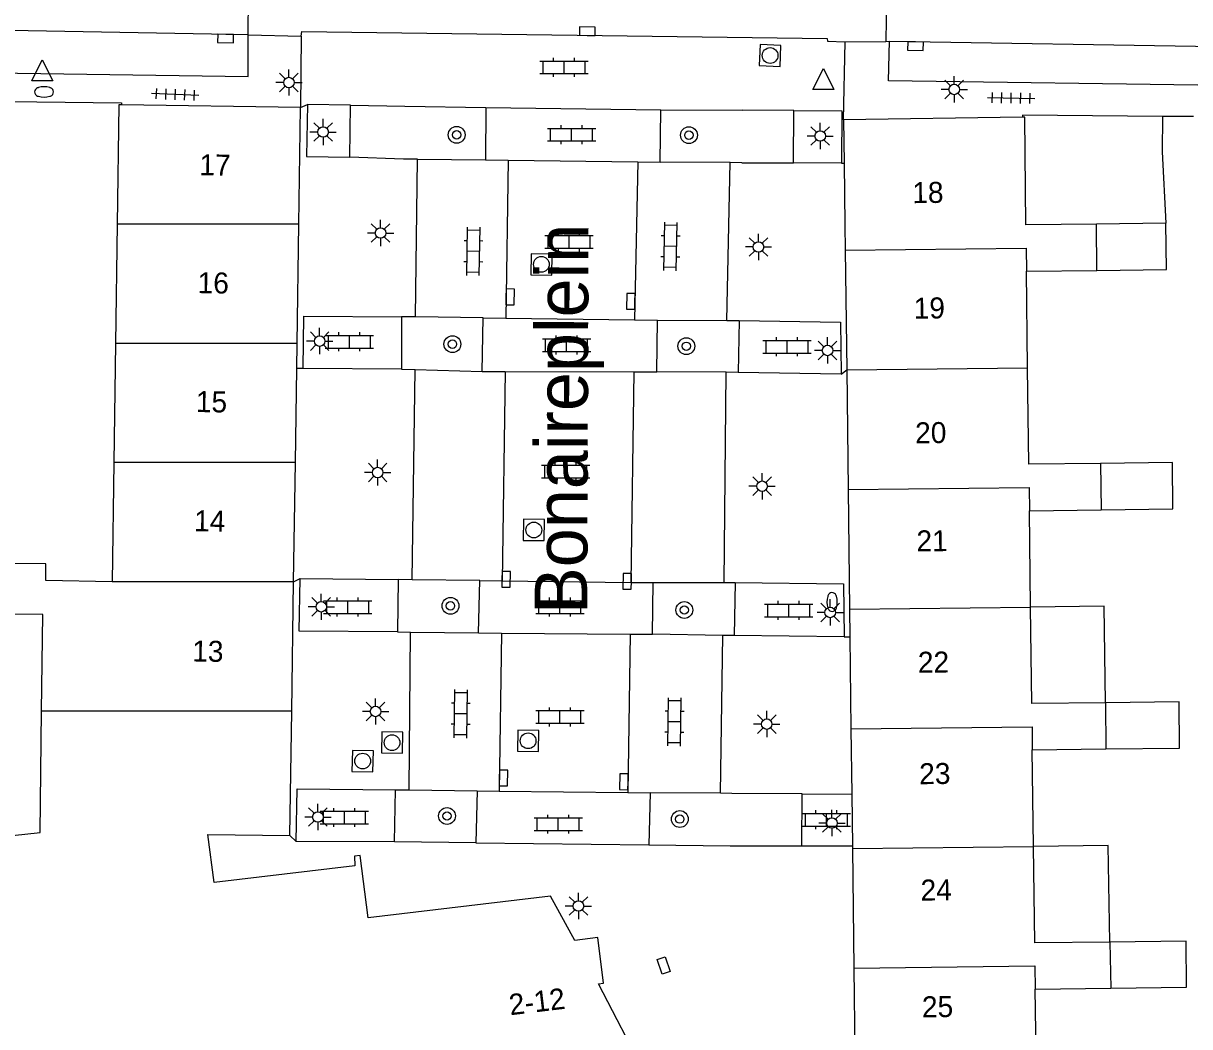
# Model space of a CAD drawing. Extents: x 132999 to 136000, y 398499 to 400501.
# Drawn here: x 133616.6 to 133672.1, y 398546.3 to 398594.1 of the extents above; entities that cross this region are included whole.
import ezdxf

# ---------------------------------------------------------------- set-up
doc = ezdxf.new("R2010")
doc.units = 0
for name, color, linetype in [('gg-afsc-erfafscheiding', 7, 'Continuous'), ('gg-afsc-muur', 7, 'Continuous'), ('gg-anno-huisnummerreeks BGT', 7, 'Continuous'), ('gg-anno-openbare ruimte label', 7, 'Continuous'), ('gg-bbg-bijgebouw', 7, 'Continuous'), ('gg-bbg-hoofdgebouw', 7, 'Continuous'), ('gg-bbg-luifel en loopbrug', 7, 'Continuous'), ('gg-bbg-tussenscheiding', 7, 'Continuous'), ('gg-knt-verharding', 7, 'Continuous'), ('gg-knt-verharding nz', 7, 'Continuous'), ('gt-grn-weggrens', 7, 'Continuous'), ('gt-symb-boom', 7, 'Continuous'), ('gt-symb-brandkraan', 7, 'Continuous'), ('gt-symb-klinker verharding', 7, 'Continuous'), ('gt-symb-kolk', 7, 'Continuous'), ('gt-symb-kolk center center', 7, 'Continuous'), ('gt-symb-lichtmast', 7, 'Continuous'), ('gt-symb-rioolschacht', 7, 'Continuous'), ('gt-symb-tegel verharding', 7, 'Continuous'), ('gt-symb-waterafsluiter', 7, 'Continuous')]:
    doc.layers.add(name, color=color, linetype=linetype)

# ---------------------------------------------------------------- blocks, each defined once
blk = doc.blocks.new('gt0-BR')
at = {"layer": 'gt-symb-brandkraan'}
for centre, radius, start, end in [((-0.244, 0), 0.206, 107.5669, 252.4331), ((0.599, -2.664), 3, 106.892, 107.5669), ((0, -0.691), 0.938, 73.108, 106.892), ((-0.599, -2.664), 3, 72.4331, 73.108), ((0.244, 0), 0.206, 287.567, 72.4331), ((0.599, 2.664), 3, 252.4331, 253.108), ((0, 0.691), 0.938, 253.108, 286.8921), ((-0.599, 2.664), 3, 286.8921, 287.567)]:
    blk.add_arc(centre, radius, start, end, dxfattribs=at)
blk = doc.blocks.new('gt0-LMAST')
at = {"layer": 'gt-symb-lichtmast'}
for p, q in [((-0.005, 0.246), (-0.005, 0.621)), ((-0.182, 0.173), (-0.447, 0.438)), ((0.172, 0.173), (0.437, 0.438)), ((-0.255, -0.004), (-0.63, -0.004)), ((-0.182, -0.181), (-0.447, -0.446)), ((-0.005, -0.254), (-0.005, -0.629)), ((0.437, -0.446), (0.172, -0.181)), ((0.245, -0.004), (0.62, -0.004))]:
    blk.add_line(p, q, dxfattribs=at)
blk.add_circle((-0.005, -0.004), 0.25, dxfattribs=at)
blk = doc.blocks.new('gt0-TEG1')
at = {"layer": 'gt-symb-tegel verharding'}
for p, q in [((-1.125, 0), (1.125, 0)), ((-0.9, -0.25), (-0.9, 0.25)), ((-0.45, -0.25), (-0.45, 0.25)), ((0, -0.25), (0, 0.25)), ((0.45, -0.25), (0.45, 0.25)), ((0.9, -0.25), (0.9, 0.25))]:
    blk.add_line(p, q, dxfattribs=at)
blk = doc.blocks.new('gt0-WAFSL')
at = {"layer": 'gt-symb-waterafsluiter'}
for p, q in [((-0.5, -0.333), (0, 0.667)), ((0, 0.667), (0.5, -0.333)), ((0.5, -0.333), (-0.5, -0.333))]:
    blk.add_line(p, q, dxfattribs=at)
blk = doc.blocks.new('gt0-KOLK')
at = {"layer": 'gt-symb-kolk'}
blk.add_lwpolyline([(0, 0), (0.375, 0), (0.375, 0.4), (-0.375, 0.4), (-0.375, 0), (0, 0)], dxfattribs=at)
blk = doc.blocks.new('gt0-KL1')
at = {"layer": 'gt-symb-klinker verharding'}
for p, q in [((-1.15, 0.3), (1.15, 0.3)), ((-1, -0.3), (-1, 0.3)), ((-0.5, 0.3), (-0.5, 0.45)), ((0, -0.3), (0, 0.3)), ((0.5, 0.3), (0.5, 0.45)), ((1, -0.3), (1, 0.3)), ((-1.15, -0.3), (1.15, -0.3)), ((-0.5, -0.45), (-0.5, -0.3)), ((0.5, -0.45), (0.5, -0.3))]:
    blk.add_line(p, q, dxfattribs=at)
blk = doc.blocks.new('gt0-RS')
at = {"layer": 'gt-symb-rioolschacht'}
blk.add_lwpolyline([(-0.5, -0.5), (0.5, -0.5), (0.5, 0.5), (-0.5, 0.5)], close=True, dxfattribs=at)
blk.add_circle((0, 0), 0.375, dxfattribs=at)
blk = doc.blocks.new('gt0-KOLKCC')
at = {"layer": 'gt-symb-kolk center center'}
blk.add_lwpolyline([(-0.375, 0.2), (0.375, 0.2), (0.375, -0.2), (-0.375, -0.2)], close=True, dxfattribs=at)
blk = doc.blocks.new('gt0-BOOM')
at = {"layer": 'gt-symb-boom'}
for radius in [0.4, 0.2]:
    blk.add_circle((0, 0), radius, dxfattribs=at)

msp = doc.modelspace()

# ---------------------------------------------------------------- linework, layer by layer
at = {"layer": 'gg-afsc-erfafscheiding'}
msp.add_line((133670.827, 398587.956), (133671.01, 398584.549), dxfattribs=at)
at = {"layer": 'gg-afsc-muur'}
msp.add_line((133670.846, 398589.624), (133670.827, 398587.956), dxfattribs=at)
for points in [[(133614.572, 398590.368), (133621.298, 398590.274), (133621.297, 398590.18)], [(133670.846, 398589.624), (133664.19, 398589.7), (133664.189, 398589.593)]]:
    msp.add_lwpolyline(points, dxfattribs=at)
at = {"layer": 'gg-bbg-bijgebouw'}
msp.add_line((133671.01, 398584.549), (133667.705, 398584.508), dxfattribs=at)
for points in [[(133667.732, 398582.306), (133671.036, 398582.347), (133671.01, 398584.549)], [(133667.929, 398570.905), (133671.343, 398570.947), (133671.319, 398573.155), (133667.903, 398573.113)], [(133668.158, 398559.518), (133671.661, 398559.561), (133671.636, 398561.762), (133668.132, 398561.719)], [(133668.393, 398548.126), (133671.992, 398548.17), (133671.97, 398550.37), (133668.35, 398550.326)]]:
    msp.add_lwpolyline(points, dxfattribs=at)
at = {"layer": 'gg-bbg-hoofdgebouw'}
for p, q in [((133629.826, 398590.055), (133621.297, 398590.18)), ((133629.744, 398584.505), (133629.826, 398590.055)), ((133664.189, 398589.593), (133655.667, 398589.474)), ((133655.667, 398589.474), (133655.696, 398587.409)), ((133621.1, 398584.505), (133621.019, 398578.828)), ((133629.66, 398578.828), (133629.744, 398584.505)), ((133655.751, 398583.268), (133655.819, 398577.567)), ((133664.375, 398582.265), (133667.732, 398582.306)), ((133664.431, 398577.668), (133664.375, 398582.265)), ((133621.019, 398578.828), (133620.939, 398573.15)), ((133629.642, 398577.638), (133629.66, 398578.828)), ((133629.576, 398573.15), (133629.642, 398577.638)), ((133655.819, 398577.567), (133655.886, 398571.869)), ((133620.939, 398573.15), (133620.858, 398567.473)), ((133629.492, 398567.473), (133629.576, 398573.15)), ((133655.886, 398571.869), (133655.953, 398566.168)), ((133664.515, 398570.863), (133667.929, 398570.905)), ((133664.571, 398566.27), (133664.515, 398570.863)), ((133629.401, 398561.312), (133629.492, 398567.473)), ((133655.953, 398566.168), (133655.968, 398564.859)), ((133655.968, 398564.859), (133656.02, 398560.477)), ((133629.313, 398555.39), (133629.401, 398561.312)), ((133656.02, 398560.477), (133656.057, 398557.371)), ((133664.654, 398559.475), (133668.158, 398559.518)), ((133664.711, 398554.878), (133664.654, 398559.475)), ((133656.057, 398557.371), (133656.087, 398554.901)), ((133656.087, 398554.901), (133656.088, 398554.777)), ((133656.088, 398554.777), (133656.155, 398549.083)), ((133656.155, 398549.083), (133656.221, 398543.472)), ((133664.794, 398548.082), (133668.393, 398548.126)), ((133664.844, 398543.987), (133664.794, 398548.082))]:
    msp.add_line(p, q, dxfattribs=at)
for points in [[(133621.297, 398590.18), (133621.181, 398590.182), (133621.1, 398584.505)], [(133667.705, 398584.508), (133664.353, 398584.467), (133664.3, 398589.595), (133664.189, 398589.593)], [(133655.696, 398587.409), (133655.737, 398584.474), (133655.751, 398583.268)], [(133667.903, 398573.113), (133664.488, 398573.071), (133664.431, 398577.668)], [(133620.858, 398567.473), (133617.696, 398567.541), (133617.697, 398568.328), (133612.025, 398568.386)], [(133617.494, 398561.312), (133617.549, 398565.927), (133612.589, 398565.969)], [(133668.132, 398561.719), (133664.627, 398561.676), (133664.571, 398566.27)], [(133614.909, 398552.815), (133614.531, 398555.957), (133614.85, 398555.991), (133614.927, 398555.27), (133617.425, 398555.536), (133617.494, 398561.312)], [(133646.218, 398544.077), (133643.998, 398548.332), (133644.246, 398548.363), (133643.974, 398550.536), (133642.872, 398550.397), (133641.715, 398552.513), (133633.036, 398551.479), (133632.655, 398554.448), (133632.386, 398554.413), (133632.406, 398553.947), (133625.716, 398553.167), (133625.414, 398555.446), (133629.313, 398555.39)], [(133668.35, 398550.326), (133664.767, 398550.282), (133664.711, 398554.878)]]:
    msp.add_lwpolyline(points, dxfattribs=at)
at = {"layer": 'gg-bbg-luifel en loopbrug'}
for points in [[(133668.132, 398561.719), (133668.078, 398566.312), (133664.571, 398566.27)], [(133668.35, 398550.326), (133668.26, 398554.92), (133664.711, 398554.878)]]:
    msp.add_lwpolyline(points, dxfattribs=at)
at = {"layer": 'gg-bbg-tussenscheiding'}
for p, q in [((133629.744, 398584.505), (133621.1, 398584.505)), ((133667.732, 398582.306), (133667.705, 398584.508)), ((133629.66, 398578.828), (133621.019, 398578.828)), ((133655.819, 398577.567), (133664.431, 398577.668)), ((133629.576, 398573.15), (133620.939, 398573.15)), ((133667.903, 398573.113), (133667.929, 398570.905)), ((133629.492, 398567.473), (133620.858, 398567.473)), ((133655.953, 398566.168), (133664.571, 398566.27)), ((133668.132, 398561.719), (133668.158, 398559.518)), ((133629.401, 398561.312), (133617.494, 398561.312)), ((133656.088, 398554.777), (133664.711, 398554.878)), ((133668.35, 398550.326), (133668.393, 398548.126))]:
    msp.add_line(p, q, dxfattribs=at)
for points in [[(133655.751, 398583.268), (133664.362, 398583.369), (133664.375, 398582.265)], [(133655.886, 398571.869), (133664.501, 398571.97), (133664.515, 398570.863)], [(133656.02, 398560.477), (133664.641, 398560.579), (133664.654, 398559.475)], [(133656.155, 398549.083), (133664.78, 398549.185), (133664.794, 398548.082)]]:
    msp.add_lwpolyline(points, dxfattribs=at)
at = {"layer": 'gg-knt-verharding'}
for p, q in [((133627.329, 398593.521), (133627.377, 398598.367)), ((133657.763, 398597.706), (133657.681, 398593.209)), ((133627.329, 398593.521), (133629.847, 398593.456)), ((133629.847, 398593.456), (133629.826, 398590.055)), ((133654.905, 398593.213), (133655.741, 398593.186)), ((133655.667, 398589.474), (133655.741, 398593.186)), ((133655.741, 398593.186), (133657.681, 398593.209)), ((133657.681, 398593.209), (133657.861, 398593.211)), ((133632.164, 398587.693), (133632.206, 398590.172)), ((133632.206, 398590.172), (133634.787, 398590.128)), ((133634.787, 398590.128), (133638.645, 398590.062)), ((133638.645, 398590.062), (133638.626, 398587.563)), ((133638.645, 398590.062), (133646.971, 398589.949)), ((133646.944, 398587.462), (133646.971, 398589.949)), ((133646.971, 398589.949), (133650.877, 398589.927)), ((133653.301, 398589.913), (133650.877, 398589.927)), ((133653.287, 398587.423), (133653.301, 398589.913)), ((133672.333, 398589.623), (133670.846, 398589.624)), ((133634.73, 398587.599), (133632.164, 398587.693)), ((133635.386, 398587.593), (133634.73, 398587.599)), ((133635.386, 398587.593), (133638.626, 398587.563)), ((133638.626, 398587.563), (133639.699, 398587.55)), ((133639.699, 398587.55), (133645.879, 398587.475)), ((133645.879, 398587.475), (133646.944, 398587.462)), ((133650.269, 398587.436), (133646.944, 398587.462)), ((133650.822, 398587.432), (133650.269, 398587.436)), ((133650.822, 398587.432), (133653.287, 398587.423)), ((133634.635, 398580.098), (133634.629, 398577.602)), ((133635.3, 398580.088), (133634.635, 398580.098)), ((133638.508, 398580.039), (133635.3, 398580.088)), ((133638.474, 398577.495), (133638.508, 398580.039)), ((133638.508, 398580.039), (133639.593, 398580.025)), ((133639.593, 398580.025), (133645.72, 398579.947)), ((133645.72, 398579.947), (133646.806, 398579.933)), ((133646.784, 398577.471), (133646.806, 398579.933)), ((133646.806, 398579.933), (133650.11, 398579.914)), ((133650.11, 398579.914), (133650.701, 398579.911)), ((133650.701, 398579.911), (133650.653, 398577.448)), ((133634.629, 398577.602), (133635.277, 398577.584)), ((133635.277, 398577.584), (133638.474, 398577.495)), ((133638.474, 398577.495), (133639.558, 398577.492)), ((133639.558, 398577.492), (133645.691, 398577.474)), ((133645.691, 398577.474), (133646.784, 398577.471)), ((133650.085, 398577.451), (133646.784, 398577.471)), ((133650.653, 398577.448), (133650.085, 398577.451)), ((133634.475, 398567.579), (133634.438, 398565.092)), ((133635.134, 398567.573), (133634.475, 398567.579)), ((133638.353, 398567.541), (133635.134, 398567.573)), ((133638.289, 398565.042), (133638.353, 398567.541)), ((133638.353, 398567.541), (133639.418, 398567.527)), ((133639.418, 398567.527), (133645.546, 398567.45)), ((133645.546, 398567.45), (133646.613, 398567.436)), ((133646.573, 398564.976), (133646.613, 398567.436)), ((133646.613, 398567.436), (133649.98, 398567.448)), ((133649.98, 398567.448), (133650.511, 398567.45)), ((133650.511, 398567.45), (133650.457, 398564.915)), ((133634.438, 398565.092), (133635.064, 398565.084)), ((133635.064, 398565.084), (133638.289, 398565.042)), ((133638.289, 398565.042), (133639.382, 398565.033)), ((133639.382, 398565.033), (133645.511, 398564.984)), ((133645.511, 398564.984), (133646.573, 398564.976)), ((133649.916, 398564.923), (133646.573, 398564.976)), ((133650.457, 398564.915), (133649.916, 398564.923)), ((133634.3, 398555.096), (133634.337, 398557.576)), ((133634.337, 398557.576), (133634.997, 398557.567)), ((133634.997, 398557.567), (133638.227, 398557.525)), ((133638.227, 398557.525), (133638.168, 398555.042)), ((133638.227, 398557.525), (133639.277, 398557.512)), ((133639.277, 398557.512), (133645.402, 398557.438)), ((133645.402, 398557.438), (133646.464, 398557.425)), ((133646.464, 398557.425), (133646.396, 398554.954)), ((133649.807, 398557.406), (133646.464, 398557.425)), ((133650.351, 398557.403), (133649.807, 398557.406)), ((133653.694, 398557.384), (133650.351, 398557.403)), ((133653.68, 398554.904), (133653.694, 398557.384)), ((133638.168, 398555.042), (133634.3, 398555.096)), ((133638.168, 398555.042), (133646.396, 398554.954)), ((133646.396, 398554.954), (133650.275, 398554.908)), ((133650.275, 398554.908), (133653.68, 398554.904))]:
    msp.add_line(p, q, dxfattribs=at)
for points in [[(133591.108, 398592.06), (133627.327, 398591.538), (133627.329, 398593.521)], [(133689.511, 398590.883), (133657.809, 398591.33), (133657.861, 398593.211)]]:
    msp.add_lwpolyline(points, dxfattribs=at)
at = {"layer": 'gg-knt-verharding nz'}
for p, q in [((133657.861, 398593.211), (133689.659, 398592.704)), ((133632.206, 398590.172), (133630.152, 398590.207)), ((133635.3, 398580.088), (133635.386, 398587.593)), ((133639.699, 398587.55), (133639.593, 398580.025)), ((133645.879, 398587.475), (133645.72, 398579.947)), ((133650.11, 398579.914), (133650.269, 398587.436)), ((133655.569, 398587.41), (133653.287, 398587.423)), ((133634.629, 398577.602), (133629.943, 398577.636)), ((133635.134, 398567.573), (133635.277, 398577.584)), ((133639.558, 398577.492), (133639.418, 398567.527)), ((133645.691, 398577.474), (133645.546, 398567.45)), ((133649.98, 398567.448), (133650.085, 398577.451)), ((133655.563, 398577.36), (133650.653, 398577.448)), ((133629.801, 398567.627), (133634.475, 398567.579)), ((133634.997, 398557.567), (133635.064, 398565.084)), ((133639.382, 398565.033), (133639.277, 398557.512)), ((133645.511, 398564.984), (133645.402, 398557.438)), ((133649.807, 398557.406), (133649.916, 398564.923)), ((133655.697, 398564.862), (133650.457, 398564.915)), ((133653.694, 398557.384), (133656.057, 398557.371)), ((133634.3, 398555.096), (133629.615, 398555.115)), ((133653.68, 398554.904), (133656.087, 398554.901))]:
    msp.add_line(p, q, dxfattribs=at)
for points in [[(133627.329, 398593.521), (133614.231, 398593.762), (133591.368, 398594.065)], [(133629.847, 398593.456), (133629.887, 398593.675), (133654.891, 398593.34), (133654.905, 398593.213)], [(133630.152, 398590.207), (133630.11, 398587.728), (133632.164, 398587.693)], [(133653.301, 398589.913), (133655.583, 398589.9), (133655.569, 398587.41)], [(133629.943, 398577.636), (133629.98, 398580.13), (133634.635, 398580.098)], [(133650.701, 398579.911), (133655.526, 398579.835), (133655.563, 398577.36)], [(133634.438, 398565.092), (133629.753, 398565.121), (133629.801, 398567.627)], [(133650.511, 398567.45), (133655.66, 398567.374), (133655.697, 398564.862)], [(133629.615, 398555.115), (133629.665, 398557.616), (133634.337, 398557.576)]]:
    msp.add_lwpolyline(points, dxfattribs=at)
at = {"layer": 'gt-grn-weggrens'}
for p, q in [((133629.826, 398590.055), (133630.152, 398590.207)), ((133655.569, 398587.41), (133655.696, 398587.409)), ((133629.943, 398577.636), (133629.642, 398577.638)), ((133655.563, 398577.36), (133655.819, 398577.567)), ((133629.492, 398567.473), (133629.801, 398567.627)), ((133655.697, 398564.862), (133655.968, 398564.859)), ((133629.313, 398555.39), (133629.615, 398555.115))]:
    msp.add_line(p, q, dxfattribs=at)

# ---------------------------------------------------------------- block references
at = {"layer": 'gt-symb-boom'}
for p in [(133637.253, 398588.758), (133648.31, 398588.743), (133637.051, 398578.792), (133648.185, 398578.693), (133636.958, 398566.334), (133648.091, 398566.134), (133636.795, 398556.327), (133647.874, 398556.181)]:
    msp.add_blockref('gt0-BOOM', p, dxfattribs=at)
at = {"layer": 'gt-symb-brandkraan'}
for p, rotation in [((133617.616, 398590.8), -0.11459140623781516), ((133655.124, 398566.513), -89.08334574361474)]:
    msp.add_blockref('gt0-BR', p, dxfattribs=dict(at, rotation=rotation))
at = {"layer": 'gt-symb-klinker verharding'}
for p in [(133642.368, 398591.973), (133642.725, 398588.765), (133642.606, 398583.657), (133632.152, 398578.905), (133642.487, 398578.746), (133652.981, 398578.667), (133642.448, 398572.727), (133632.072, 398566.272), (133642.17, 398566.272), (133653.06, 398566.114), (133642.17, 398561.045), (133631.914, 398556.254), (133654.856, 398556.147), (133642.091, 398555.937)]:
    msp.add_blockref('gt0-KL1', p, dxfattribs=at)
for p, rotation in [((133638.049, 398583.209), 89.19791148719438), ((133647.433, 398583.443), 88.79696545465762), ((133637.447, 398561.189), 89.19791148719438), ((133647.619, 398560.806), 89.19791148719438)]:
    msp.add_blockref('gt0-KL1', p, dxfattribs=dict(at, rotation=rotation))
at = {"layer": 'gt-symb-kolk'}
for p, rotation in [((133643.473, 398593.492), -0.7448031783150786), ((133626.259, 398593.54), 178.96878733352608), ((133659.1, 398593.184), 178.73969615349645), ((133639.598, 398581.045), -90.91665425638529), ((133645.739, 398580.825), 88.79696545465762), ((133639.408, 398567.598), -90.80208851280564), ((133645.571, 398567.494), 89.25519682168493), ((133639.281, 398558.139), -90.74480317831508), ((133645.415, 398557.954), 89.08334574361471)]:
    msp.add_blockref('gt0-KOLK', p, dxfattribs=dict(at, rotation=rotation))
at = {"layer": 'gt-symb-kolk center center', "rotation": 108.90606099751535}
msp.add_blockref('gt0-KOLKCC', (133647.103, 398549.209), dxfattribs=at)
at = {"layer": 'gt-symb-lichtmast'}
for p in [(133629.275, 398591.253), (133660.943, 398590.924), (133630.903, 398588.896), (133654.562, 398588.706), (133633.637, 398584.087), (133651.625, 398583.422), (133630.738, 398578.941), (133654.911, 398578.496), (133633.498, 398572.683), (133651.797, 398572.031), (133630.815, 398566.29), (133655.037, 398566.022), (133633.398, 398561.306), (133652.018, 398560.705), (133630.654, 398556.282), (133655.121, 398555.995), (133643.055, 398552.043)]:
    msp.add_blockref('gt0-LMAST', p, dxfattribs=at)
at = {"layer": 'gt-symb-rioolschacht'}
for p, rotation in [((133652.172, 398592.533), -2.292900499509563), ((133641.287, 398582.59), -91.0884888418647), ((133640.928, 398569.945), 89.31248364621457), ((133640.655, 398559.907), 89.14062775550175), ((133634.179, 398559.819), -90.80208851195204), ((133632.781, 398558.942), -91.203034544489)]:
    msp.add_blockref('gt0-RS', p, dxfattribs=dict(at, rotation=rotation))
at = {"layer": 'gt-symb-tegel verharding'}
for p, rotation in [((133623.852, 398590.679), 177.64984047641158), ((133663.646, 398590.512), -1.2030345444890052)]:
    msp.add_blockref('gt0-TEG1', p, dxfattribs=dict(at, rotation=rotation))
at = {"layer": 'gt-symb-waterafsluiter'}
for p in [(133617.527, 398591.659), (133654.714, 398591.257)]:
    msp.add_blockref('gt0-WAFSL', p, dxfattribs=at)

# ---------------------------------------------------------------- texts
at = {"layer": 'gg-anno-huisnummerreeks BGT'}
for s, rotation, p in [('17', 359.1, (133625.001, 398586.836)), ('18', 0.8, (133658.946, 398585.502)), ('16', 359.1, (133624.918, 398581.222)), ('19', 0.7, (133659.013, 398580.003)), ('15', 359.1, (133624.834, 398575.56)), ('20', 0.7, (133659.083, 398574.067)), ('14', 359.1, (133624.75, 398569.883)), ('21', 0.7, (133659.144, 398568.92)), ('13', 359.1, (133624.659, 398563.685)), ('22', 0.7, (133659.212, 398563.142)), ('23', 0.7, (133659.275, 398557.837)), ('24', 0.7, (133659.34, 398552.296)), ('2-12', 6.8, (133639.805, 398546.836)), ('25', 0.7, (133659.406, 398546.738))]:
    msp.add_text(s, height=1, rotation=rotation, dxfattribs=at).set_placement(p)
at = {"layer": 'gg-anno-openbare ruimte label'}
msp.add_text('Bonaireplein', height=2.5, rotation=89.8, dxfattribs=at).set_placement((133643.465, 398565.935))

doc.saveas('drawing.dxf')
